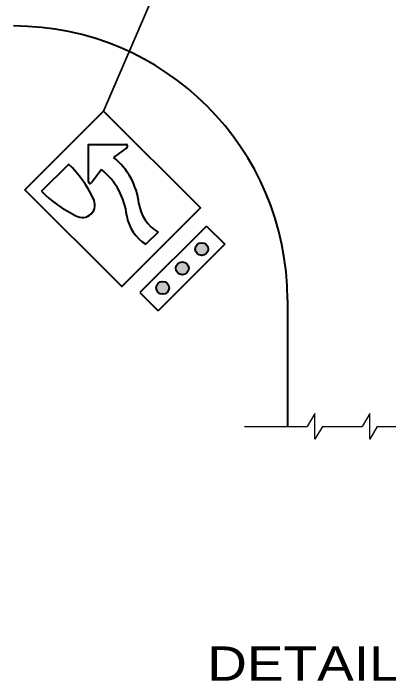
# Model space of a CAD drawing. Extents: x 1081 to 1936, y -630 to -24.
# Drawn here: x 1299 to 1351.6, y -330.3 to -236.7 of the extents above; entities that cross this region are included whole.
import ezdxf
from ezdxf.enums import TextEntityAlignment as Align

# ---------------------------------------------------------------- set-up
doc = ezdxf.new("R2010")
doc.units = 0
doc.layers.add('1', color=7, linetype='Continuous', lineweight=53)

msp = doc.modelspace()

# ---------------------------------------------------------------- hatches: boundary and pattern name
at = {"layer": '1'}
for points in [[(1326.287, -269.727, 1), (1324.487, -269.727, 1)], [(1323.554, -272.423, 1), (1321.754, -272.423, 1)], [(1320.82, -275.158, 1), (1319.02, -275.158, 1)]]:
    msp.add_hatch(color=256, dxfattribs=at).paths.add_polyline_path(points)

# ---------------------------------------------------------------- linework, layer by layer
at = {"layer": '1', "lineweight": 35}
msp.add_line((1323.967, -221.771), (1311.628, -250.373), dxfattribs=at)
at = {"layer": '1', "lineweight": 40}
for p, q in [((1314.919, -255.473), (1313.03, -256.866)), ((1302.931, -261.615), (1306.749, -257.797)), ((1311.333, -258.563), (1309.94, -260.452)), ((1326.053, -266.494), (1316.719, -275.828)), ((1326.053, -266.494), (1328.599, -269.04)), ((1319.265, -267.343), (1317.568, -269.04)), ((1328.599, -269.04), (1319.265, -278.374)), ((1316.719, -275.828), (1319.265, -278.374)), ((1337.393, -276.837), (1337.393, -294.597))]:
    msp.add_line(p, q, dxfattribs=at)
at = {"layer": '1', "lineweight": 25}
for p, q in [((1341.233, -292.797), (1340.179, -294.597)), ((1341.233, -296.397), (1341.233, -292.797)), ((1348.913, -292.797), (1347.859, -294.597)), ((1348.913, -296.397), (1348.913, -292.797)), ((1331.393, -294.597), (1337.393, -294.597)), ((1337.393, -294.597), (1340.179, -294.597)), ((1342.287, -294.597), (1341.233, -296.397)), ((1349.967, -294.597), (1348.913, -296.397)), ((1349.967, -294.597), (1352.753, -294.597))]:
    msp.add_line(p, q, dxfattribs=at)
at = {"layer": '1', "lineweight": 40}
msp.add_lwpolyline([(1300.597, -261.403), (1311.628, -250.373), (1325.205, -263.949), (1314.174, -274.98)], close=True, dxfattribs=at)
msp.add_lwpolyline([(1309.507, -260.309), (1309.507, -255.039), (1314.777, -255.039)], dxfattribs=at)
at = {"layer": '1', "lineweight": 25}
msp.add_lwpolyline([(1342.287, -294.597), (1345.073, -294.597), (1347.859, -294.597)], dxfattribs=at)
at = {"layer": '1', "lineweight": 40}
for centre in [(1325.387, -269.727), (1322.654, -272.423), (1319.92, -275.158)]:
    msp.add_circle(centre, 0.9, dxfattribs=at)
for centre, radius, start, end in [((1298.993, -276.835), 38.4, 0, 90), ((1314.777, -255.279), 0.24, 306.40525, 90), ((1307.012, -264.367), 9.617, 6.10806, 51.26016), ((1295.135, -269.706), 16.618, 25.28501, 45.72037), ((1305.315, -266.064), 9.617, 6.10806, 51.26016), ((1309.747, -260.309), 0.24, 179.99403, 323.59761), ((1316.061, -248.286), 18.71, 225.43251, 243.56211), ((1308.652, -263.53), 1.769, 238.60951, 31.39048), ((1322.146, -262.5), 5.635, 188.60534, 239.2536), ((1320.449, -264.197), 5.635, 188.60534, 239.2536)]:
    msp.add_arc(centre, radius, start, end, dxfattribs=at)

# ---------------------------------------------------------------- texts
at = {"layer": '1', "width": 1.2}
msp.add_text('DETAIL "A"', height=4.8, dxfattribs=at).set_placement((1346.006, -330.262), align=Align.CENTER)

doc.saveas('drawing.dxf')
